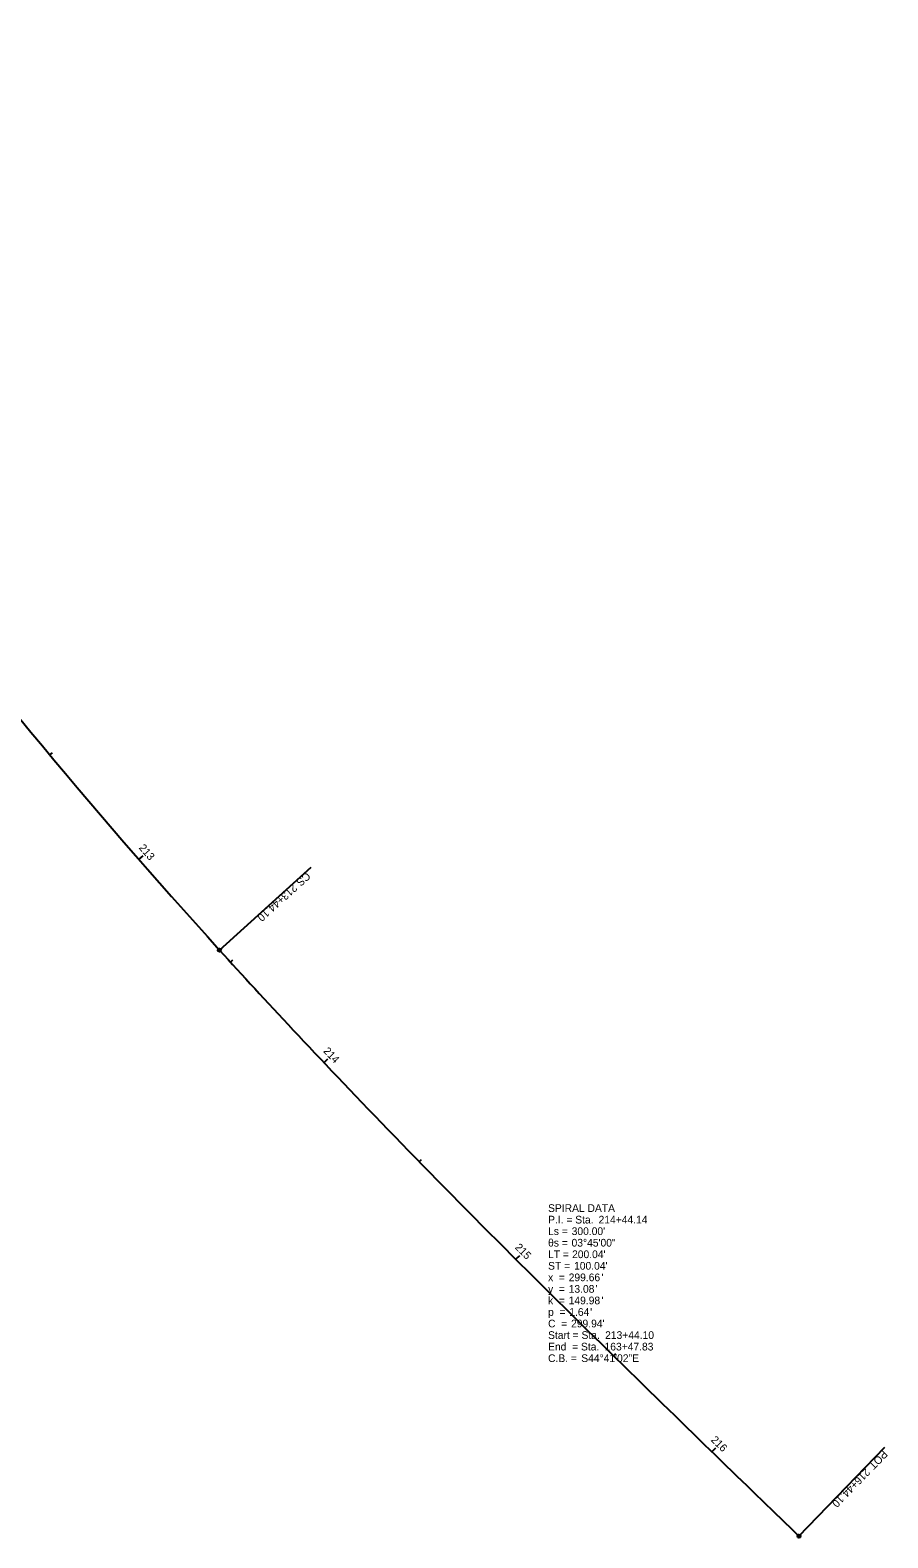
# Model space of a CAD drawing. Extents: x 2297881 to 2300632, y 559916 to 564460.
# Drawn here: x 2300320 to 2300632, y 559916 to 560465 of the extents above; entities that cross this region are included whole.
import ezdxf

# ---------------------------------------------------------------- set-up
doc = ezdxf.new("R2010")
doc.units = 0
for name, color, linetype in [('GE_X_Alignment', 7, 'Continuous'), ('GE_X_Alignment_1000_Cardinal_Points', 7, 'Continuous'), ('GE_X_Alignment_1000_Curve_Data', 7, 'Continuous'), ('GE_X_Alignment_1000_Stations', 7, 'Continuous'), ('GE_X_Alignment_100_Cardinal_Points', 7, 'Continuous'), ('GE_X_Alignment_100_Curve_Data', 7, 'Continuous'), ('GE_X_Alignment_100_Stations', 7, 'Continuous'), ('GE_X_Alignment_500_Cardinal_Points', 7, 'Continuous'), ('GE_X_Alignment_500_Curve_Data', 7, 'Continuous'), ('GE_X_Alignment_500_Stations', 7, 'Continuous')]:
    doc.layers.add(name, color=color, linetype=linetype)

msp = doc.modelspace()

# ---------------------------------------------------------------- linework, layer by layer
at = {"layer": 'GE_X_Alignment'}
msp.add_arc((2302087.44, 561669.34), 2291.83, 211.7005, 222.18383, dxfattribs=at)
msp.add_open_spline([(2300389.21, 560130.35), (2300397.6, 560121.08), (2300414.54, 560102.7), (2300448.94, 560066.41), (2300492.77, 560021.85), (2300537.33, 559978.02), (2300573.18, 559943.17), (2300591.15, 559925.78), (2300600.13, 559917.09)], degree=3, dxfattribs=at)
at = {"layer": 'GE_X_Alignment_1000_Cardinal_Points'}
for p, q in [((2300389.21, 560130.35), (2300422.55, 560160.56)), ((2300600.13, 559917.09), (2300631.42, 559949.42))]:
    msp.add_line(p, q, dxfattribs=at)
for centre in [(2300389.21, 560130.35), (2300600.13, 559917.09)]:
    msp.add_circle(centre, 0.6, dxfattribs=at)
at = {"layer": 'GE_X_Alignment_1000_Stations'}
msp.add_line((2300497.09, 560017.82), (2300497.94, 560018.67), dxfattribs=at)
at = {"layer": 'GE_X_Alignment_100_Cardinal_Points'}
for p, q in [((2300389.21, 560130.35), (2300422.55, 560160.56)), ((2300600.13, 559917.09), (2300631.42, 559949.42))]:
    msp.add_line(p, q, dxfattribs=at)
for centre in [(2300389.21, 560130.35), (2300600.13, 559917.09)]:
    msp.add_circle(centre, 0.6, dxfattribs=at)
at = {"layer": 'GE_X_Alignment_100_Stations'}
for p, q in [((2300327.47, 560201.35), (2300328.39, 560202.12)), ((2300359.91, 560163.31), (2300361.42, 560164.62)), ((2300393.18, 560125.98), (2300394.07, 560126.79)), ((2300427.22, 560089.36), (2300428.67, 560090.73)), ((2300461.9, 560053.34), (2300462.76, 560054.18)), ((2300497.09, 560017.82), (2300498.51, 560019.24)), ((2300532.66, 559982.68), (2300533.5, 559983.53)), ((2300568.46, 559947.77), (2300569.85, 559949.21))]:
    msp.add_line(p, q, dxfattribs=at)
at = {"layer": 'GE_X_Alignment_500_Cardinal_Points'}
for p, q in [((2300389.21, 560130.35), (2300422.55, 560160.56)), ((2300600.13, 559917.09), (2300631.42, 559949.42))]:
    msp.add_line(p, q, dxfattribs=at)
for centre in [(2300389.21, 560130.35), (2300600.13, 559917.09)]:
    msp.add_circle(centre, 0.6, dxfattribs=at)
at = {"layer": 'GE_X_Alignment_500_Stations'}
for p, q in [((2300359.91, 560163.31), (2300360.82, 560164.09)), ((2300427.22, 560089.36), (2300428.09, 560090.18)), ((2300497.09, 560017.82), (2300498.51, 560019.24)), ((2300568.46, 559947.77), (2300569.29, 559948.63))]:
    msp.add_line(p, q, dxfattribs=at)

# ---------------------------------------------------------------- texts
at = {"layer": 'GE_X_Alignment_1000_Cardinal_Points'}
for s, rotation, p in [('213+44.10', 222.1838, (2300415.96, 560154.52)), ('CS', 222.1838, (2300420.79, 560158.9)), ('POT', 225.9338, (2300630.68, 559948.58)), ('216+44.10', 225.9338, (2300624.33, 559942.02))]:
    msp.add_text(s, height=2.8, rotation=rotation, dxfattribs=at).set_placement(p)
at = {"layer": 'GE_X_Alignment_1000_Curve_Data'}
for s, p in [('SPIRAL DATA', (2300508.81, 560035.06)), ('P.I. = Sta. ', (2300508.81, 560030.86)), ('214+44.14', (2300527.18, 560030.86)), ('Ls = ', (2300508.81, 560026.66)), ("300.00'", (2300517.4, 560026.66)), ('θs = ', (2300508.81, 560022.46)), ('03°45\'00"', (2300517.35, 560022.46)), ('ST = ', (2300508.81, 560014.06)), ('LT = ', (2300508.81, 560018.26)), ("200.04'", (2300517.54, 560018.26)), ("100.04'", (2300518.27, 560014.06)), ('x  = ', (2300508.81, 560009.86)), ('299.66', (2300516.31, 560009.86)), ("'", (2300528.27, 560009.86)), ('y  = ', (2300508.81, 560005.66)), ('13.08', (2300516.31, 560005.66)), ("'", (2300526.1, 560005.66)), ('p  = ', (2300508.81, 559997.26)), ('k  = ', (2300508.81, 560001.46)), ('149.98', (2300516.31, 560001.46)), ('1.64', (2300516.53, 559997.26)), ("'", (2300524.14, 559997.26)), ("'", (2300528.27, 560001.46)), ('C  = ', (2300508.81, 559993.06)), ("299.94'", (2300517.18, 559993.06)), ('Start = Sta. ', (2300508.81, 559988.86)), ('213+44.10', (2300529.57, 559988.86)), ('C.B. = ', (2300508.81, 559980.46)), ('End  = Sta. ', (2300508.81, 559984.66)), ('S44°41\'02"E', (2300520.88, 559980.46)), ('163+47.83', (2300529.36, 559984.66))]:
    msp.add_text(s, height=2.8, dxfattribs=at).set_placement(p)
at = {"layer": 'GE_X_Alignment_100_Cardinal_Points'}
for s, rotation, p in [('213+44.10', 222.1838, (2300415.96, 560154.52)), ('CS', 222.1838, (2300420.79, 560158.9)), ('POT', 225.9338, (2300630.68, 559948.58)), ('216+44.10', 225.9338, (2300624.33, 559942.02))]:
    msp.add_text(s, height=2.8, rotation=rotation, dxfattribs=at).set_placement(p)
at = {"layer": 'GE_X_Alignment_100_Curve_Data'}
for s, p in [('SPIRAL DATA', (2300508.81, 560035.06)), ('P.I. = Sta. ', (2300508.81, 560030.86)), ('214+44.14', (2300527.18, 560030.86)), ('Ls = ', (2300508.81, 560026.66)), ("300.00'", (2300517.4, 560026.66)), ('θs = ', (2300508.81, 560022.46)), ('03°45\'00"', (2300517.35, 560022.46)), ('ST = ', (2300508.81, 560014.06)), ('LT = ', (2300508.81, 560018.26)), ("200.04'", (2300517.54, 560018.26)), ("100.04'", (2300518.27, 560014.06)), ('x  = ', (2300508.81, 560009.86)), ('299.66', (2300516.31, 560009.86)), ("'", (2300528.27, 560009.86)), ('y  = ', (2300508.81, 560005.66)), ('13.08', (2300516.31, 560005.66)), ("'", (2300526.1, 560005.66)), ('p  = ', (2300508.81, 559997.26)), ('k  = ', (2300508.81, 560001.46)), ('149.98', (2300516.31, 560001.46)), ('1.64', (2300516.53, 559997.26)), ("'", (2300524.14, 559997.26)), ("'", (2300528.27, 560001.46)), ('C  = ', (2300508.81, 559993.06)), ("299.94'", (2300517.18, 559993.06)), ('Start = Sta. ', (2300508.81, 559988.86)), ('213+44.10', (2300529.57, 559988.86)), ('C.B. = ', (2300508.81, 559980.46)), ('End  = Sta. ', (2300508.81, 559984.66)), ('S44°41\'02"E', (2300520.88, 559980.46)), ('163+47.83', (2300529.36, 559984.66))]:
    msp.add_text(s, height=2.8, dxfattribs=at).set_placement(p)
at = {"layer": 'GE_X_Alignment_100_Stations'}
for s, rotation, p in [('213', 311.0814, (2300359.69, 560167.44)), ('214', 313.4512, (2300426.81, 560093.43)), ('215', 315.0687, (2300496.56, 560021.95)), ('216', 315.8528, (2300567.87, 559951.89))]:
    msp.add_text(s, height=2.8, rotation=rotation, dxfattribs=at).set_placement(p)
at = {"layer": 'GE_X_Alignment_500_Cardinal_Points'}
for s, rotation, p in [('213+44.10', 222.1838, (2300415.96, 560154.52)), ('CS', 222.1838, (2300420.79, 560158.9)), ('POT', 225.9338, (2300630.68, 559948.58)), ('216+44.10', 225.9338, (2300624.33, 559942.02))]:
    msp.add_text(s, height=2.8, rotation=rotation, dxfattribs=at).set_placement(p)
at = {"layer": 'GE_X_Alignment_500_Curve_Data'}
for s, p in [('SPIRAL DATA', (2300508.81, 560035.06)), ('P.I. = Sta. ', (2300508.81, 560030.86)), ('214+44.14', (2300527.18, 560030.86)), ('Ls = ', (2300508.81, 560026.66)), ("300.00'", (2300517.4, 560026.66)), ('θs = ', (2300508.81, 560022.46)), ('03°45\'00"', (2300517.35, 560022.46)), ('ST = ', (2300508.81, 560014.06)), ('LT = ', (2300508.81, 560018.26)), ("200.04'", (2300517.54, 560018.26)), ("100.04'", (2300518.27, 560014.06)), ('x  = ', (2300508.81, 560009.86)), ('299.66', (2300516.31, 560009.86)), ("'", (2300528.27, 560009.86)), ('y  = ', (2300508.81, 560005.66)), ('13.08', (2300516.31, 560005.66)), ("'", (2300526.1, 560005.66)), ('p  = ', (2300508.81, 559997.26)), ('k  = ', (2300508.81, 560001.46)), ('149.98', (2300516.31, 560001.46)), ('1.64', (2300516.53, 559997.26)), ("'", (2300524.14, 559997.26)), ("'", (2300528.27, 560001.46)), ('C  = ', (2300508.81, 559993.06)), ("299.94'", (2300517.18, 559993.06)), ('Start = Sta. ', (2300508.81, 559988.86)), ('213+44.10', (2300529.57, 559988.86)), ('C.B. = ', (2300508.81, 559980.46)), ('End  = Sta. ', (2300508.81, 559984.66)), ('S44°41\'02"E', (2300520.88, 559980.46)), ('163+47.83', (2300529.36, 559984.66))]:
    msp.add_text(s, height=2.8, dxfattribs=at).set_placement(p)
at = {"layer": 'GE_X_Alignment_500_Stations'}
msp.add_text('215', height=2.8, rotation=315.0687, dxfattribs=at).set_placement((2300496.56, 560021.95))

doc.saveas('drawing.dxf')
